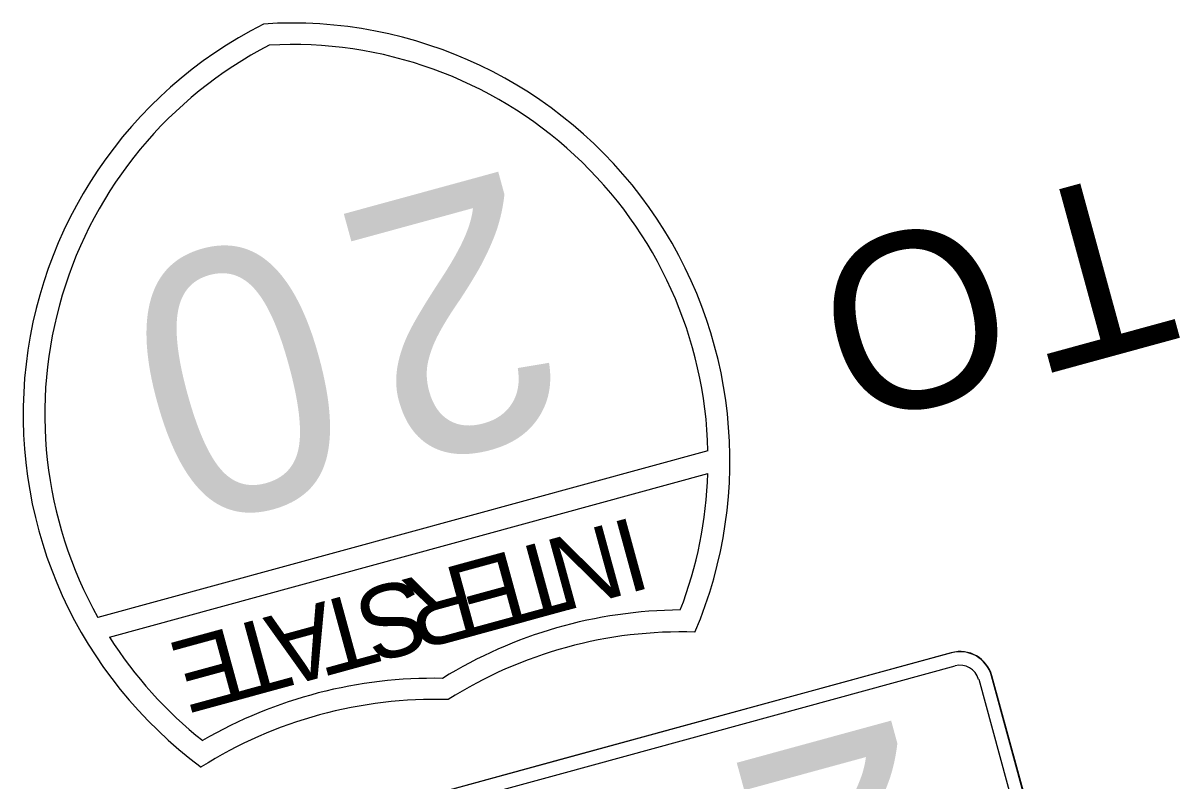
# Model space of a CAD drawing. Extents: x 2001876 to 2025694, y 804561 to 868938.
# Drawn here: x 2011151.2 to 2011251.6, y 826754.9 to 826820.7 of the extents above; entities that cross this region are included whole.
import ezdxf

# ---------------------------------------------------------------- set-up
doc = ezdxf.new("R2010")
doc.units = 0
doc.layers.add('TR SN EXTRUDED PANEL SIGNS- MOUNTED OVERHEAD', color=7, linetype='Continuous')

msp = doc.modelspace()

# ---------------------------------------------------------------- linework, layer by layer
at = {"layer": 'TR SN EXTRUDED PANEL SIGNS- MOUNTED OVERHEAD'}
for p, q in [((2011210.62, 826783.53), (2011157.68, 826769.06)), ((2011158.69, 826767.36), (2011210.61, 826781.56)), ((2011231.72, 826765.99), (2011163.95, 826747.46)), ((2011245.75, 826725.5), (2011235.23, 826763.99)), ((2011235.26, 826764), (2011235.26, 826764)), ((2011234.11, 826763.69), (2011234.12, 826763.69)), ((2011234.12, 826763.69), (2011243.31, 826730.04)), ((2011197.62, 826756.67), (2011163.99, 826747.47))]:
    msp.add_line(p, q, dxfattribs=at)
for points in [[(2011231.76, 826766), (2011231.76, 826766), (2011197.62, 826756.67)], [(2011164.3, 826746.33), (2011164.3, 826746.33), (2011197.93, 826755.52), (2011232.07, 826764.85), (2011232.07, 826764.85)], [(2011245.78, 826725.51), (2011245.78, 826725.51), (2011235.26, 826764)]]:
    msp.add_lwpolyline(points, dxfattribs=at)
for centre, radius, start, end in [((2011189.19, 826786.67), 38, 116.8259, 233.6199), ((2011174.53, 826782.67), 38, 336.9578, 93.7518), ((2011189.17, 826786.71), 36.1, 117.4264, 209.2727), ((2011174.53, 826782.71), 36.1, 1.3045, 93.1513), ((2011174.53, 826782.67), 36.1, 338.966, 358.2391), ((2011208.52, 826729.81), 39.9, 90.4269, 121.668), ((2011189.19, 826786.67), 36.1, 212.3382, 231.6116), ((2011208.37, 826729.81), 38, 88.2978, 122.2799), ((2011232.48, 826763.24), 2.85, 15.2892, 105.2889), ((2011232.51, 826763.25), 2.85, 15.2892, 105.2889), ((2011232.51, 826763.25), 1.66, 15.2892, 105.2888), ((2011186.81, 826723.88), 39.9, 88.9097, 120.1508), ((2011186.94, 826723.95), 38, 88.2978, 122.2799)]:
    msp.add_arc(centre, radius, start, end, dxfattribs=at)

# ---------------------------------------------------------------- texts
for s, height, p in [('2', 22.8, (2011193.9, 826808.17)), ('T', 15.2, (2011248.01, 826808.13)), ('O', 15.2, (2011234.22, 826804.36)), ('0', 22.8, (2011175, 826803.01)), ('N', 6.33, (2011202.08, 826777.25)), ('I', 6.33, (2011204.22, 826777.84)), ('T', 6.33, (2011197.7, 826776.06)), ('E', 6.33, (2011193.62, 826774.94)), ('R', 6.33, (2011189.53, 826773.82)), ('S', 6.33, (2011185.16, 826772.63)), ('A', 6.33, (2011177.38, 826770.5)), ('T', 6.33, (2011180.79, 826771.43)), ('E', 6.33, (2011169.13, 826768.25)), ('T', 6.33, (2011173.22, 826769.37)), ('2', 22.8, (2011228, 826760.51))]:
    msp.add_text(s, height=height, rotation=195.2888, dxfattribs=at).set_placement(p)

doc.saveas('drawing.dxf')
